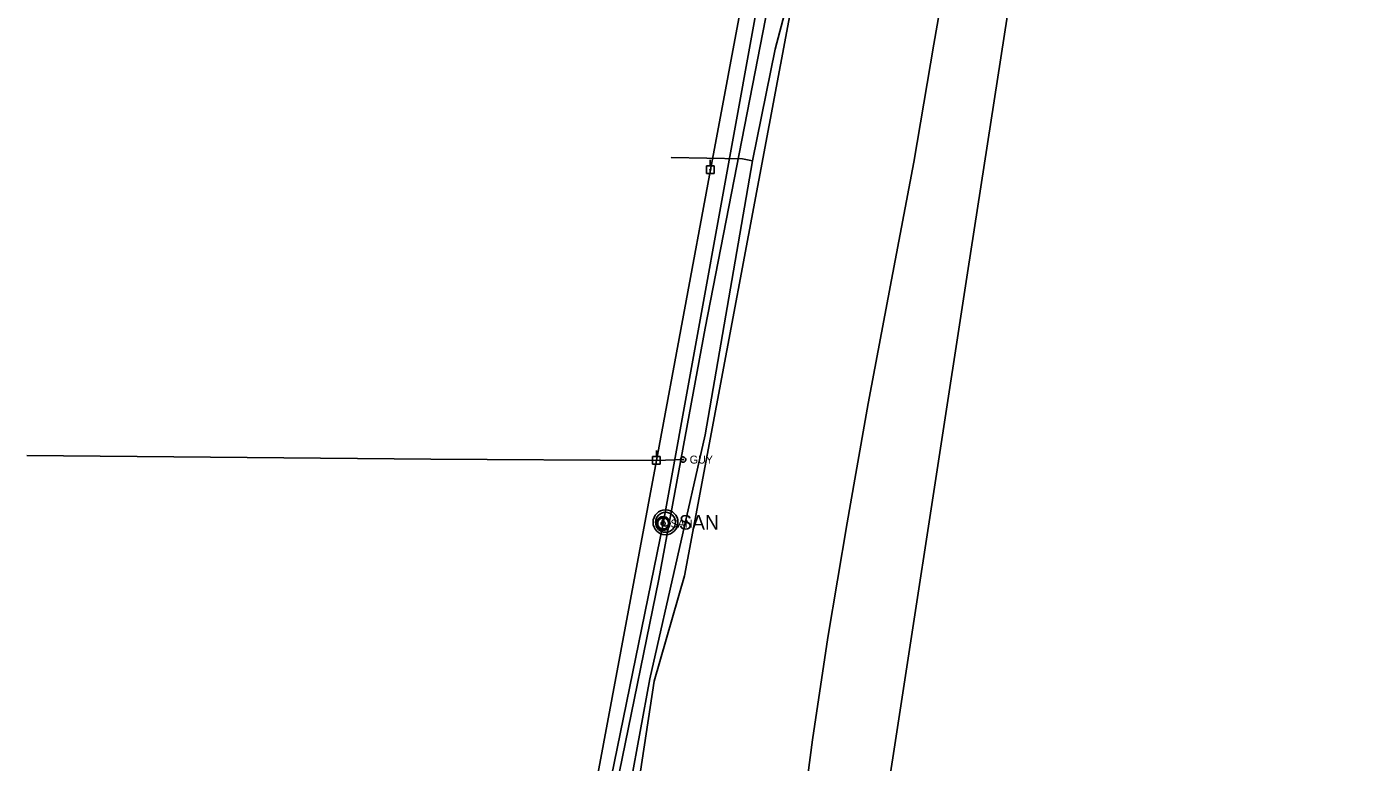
# Model space of a CAD drawing. Extents: x 600849 to 606371, y 330010 to 403088.
# Drawn here: x 601573 to 602215, y 355969 to 356323 of the extents above; entities that cross this region are included whole.
import ezdxf

# ---------------------------------------------------------------- set-up
doc = ezdxf.new("R2010")
doc.units = 0
for name, color, linetype in [('E_FTMS_Conduit', 7, 'Continuous'), ('E_UTL_EGuyWire', 7, 'Continuous'), ('E_UTL_EPowerPole', 7, 'Continuous'), ('E_UTL_FO_UG_QWEST', 7, 'Continuous'), ('E_UTL_G_UG', 7, 'Continuous'), ('E_UTL_Overhead', 7, 'Continuous'), ('E_UTL_SAN', 7, 'Continuous'), ('E_UTL_SAN_UG', 7, 'Continuous'), ('E_UTL_T_UG', 7, 'Continuous')]:
    doc.layers.add(name, color=color, linetype=linetype)

msp = doc.modelspace()

# ---------------------------------------------------------------- linework, layer by layer
at = {"layer": 'E_FTMS_Conduit'}
msp.add_lwpolyline([(601982.31, 355922.69), (602025.74, 356205), (602072.04, 356504.09), (602115.89, 356782.89), (602162.05, 357069.13), (602196.81, 357307.9), (602214.61, 357448.42)], dxfattribs=at)
at = {"layer": 'E_UTL_EGuyWire'}
msp.add_line((601888.89, 356115.12), (601876.1, 356114.7), dxfattribs=at)
for points in [[(601890.17, 356115.12), (601890.15, 356115.36), (601890.08, 356115.59), (601889.97, 356115.81), (601889.82, 356116), (601889.63, 356116.16), (601889.42, 356116.29), (601889.19, 356116.36), (601888.95, 356116.4), (601888.7, 356116.39), (601888.47, 356116.33), (601888.24, 356116.23), (601888.05, 356116.09), (601887.88, 356115.91), (601887.75, 356115.71), (601887.65, 356115.48), (601887.61, 356115.24), (601887.61, 356115), (601887.65, 356114.76), (601887.75, 356114.53), (601887.88, 356114.32), (601888.05, 356114.15), (601888.24, 356114.01), (601888.47, 356113.91), (601888.7, 356113.85), (601888.95, 356113.84), (601889.19, 356113.87), (601889.42, 356113.95), (601889.63, 356114.07), (601889.82, 356114.23), (601889.97, 356114.42), (601890.08, 356114.64), (601890.15, 356114.87), (601890.17, 356115.12)], [(601889.05, 356115.12), (601889.04, 356115.15), (601889.04, 356115.18), (601889.02, 356115.2), (601889, 356115.23), (601888.98, 356115.25), (601888.95, 356115.26), (601888.92, 356115.27), (601888.89, 356115.28), (601888.86, 356115.28), (601888.83, 356115.27), (601888.81, 356115.26), (601888.78, 356115.24), (601888.76, 356115.22), (601888.74, 356115.19), (601888.73, 356115.16), (601888.73, 356115.13), (601888.73, 356115.1), (601888.73, 356115.07), (601888.74, 356115.04), (601888.76, 356115.02), (601888.78, 356115), (601888.81, 356114.98), (601888.83, 356114.97), (601888.86, 356114.96), (601888.89, 356114.96), (601888.92, 356114.96), (601888.95, 356114.97), (601888.98, 356114.99), (601889, 356115.01), (601889.02, 356115.03), (601889.04, 356115.06), (601889.04, 356115.09), (601889.05, 356115.12)]]:
    msp.add_lwpolyline(points, dxfattribs=at)
at = {"layer": 'E_UTL_EPowerPole'}
for points in [[(601901.99, 356256.42), (601901.99, 356259.33)], [(601903.84, 356256.42), (601900.15, 356256.42)], [(601900.15, 356256.42), (601900.15, 356252.73)], [(601900.15, 356252.73), (601903.84, 356252.73)], [(601902.26, 356254.58), (601902.26, 356254.62), (601902.25, 356254.67), (601902.23, 356254.71), (601902.2, 356254.74), (601902.16, 356254.77), (601902.13, 356254.79), (601902.08, 356254.81), (601902.04, 356254.82), (601901.99, 356254.81), (601901.95, 356254.8), (601901.91, 356254.78), (601901.87, 356254.76), (601901.84, 356254.72), (601901.81, 356254.69), (601901.8, 356254.64), (601901.79, 356254.6), (601901.79, 356254.55), (601901.8, 356254.51), (601901.81, 356254.47), (601901.84, 356254.43), (601901.87, 356254.4), (601901.91, 356254.37), (601901.95, 356254.35), (601901.99, 356254.34), (601902.04, 356254.34), (601902.08, 356254.35), (601902.13, 356254.36), (601902.16, 356254.38), (601902.2, 356254.41), (601902.23, 356254.45), (601902.25, 356254.49), (601902.26, 356254.53), (601902.26, 356254.58)], [(601903.84, 356252.73), (601903.84, 356256.42)], [(601876.06, 356116.54), (601876.06, 356119.45)], [(601877.91, 356116.54), (601874.22, 356116.54)], [(601874.22, 356116.54), (601874.22, 356112.85)], [(601874.22, 356112.85), (601877.91, 356112.85)], [(601876.33, 356114.7), (601876.33, 356114.74), (601876.32, 356114.79), (601876.3, 356114.83), (601876.27, 356114.86), (601876.23, 356114.89), (601876.2, 356114.91), (601876.15, 356114.93), (601876.11, 356114.94), (601876.06, 356114.93), (601876.02, 356114.92), (601875.98, 356114.9), (601875.94, 356114.88), (601875.91, 356114.85), (601875.88, 356114.81), (601875.87, 356114.76), (601875.86, 356114.72), (601875.86, 356114.67), (601875.87, 356114.63), (601875.88, 356114.59), (601875.91, 356114.55), (601875.94, 356114.52), (601875.98, 356114.49), (601876.02, 356114.47), (601876.06, 356114.46), (601876.11, 356114.46), (601876.15, 356114.47), (601876.2, 356114.48), (601876.23, 356114.5), (601876.27, 356114.53), (601876.3, 356114.57), (601876.32, 356114.61), (601876.33, 356114.65), (601876.33, 356114.7)], [(601877.91, 356112.85), (601877.91, 356116.54)]]:
    msp.add_lwpolyline(points, dxfattribs=at)
at = {"layer": 'E_UTL_FO_UG_QWEST'}
msp.add_lwpolyline([(601944.01, 355926.93), (601951.12, 355980.3), (601958.59, 356029.58), (601967.76, 356084.77), (601971.53, 356105.69), (601977.93, 356142.12), (601989.06, 356201.56), (601999.81, 356258.26), (602009.42, 356314.96), (602018.86, 356368.21), (602029.07, 356415.09), (602035.02, 356458.54), (602045.75, 356506.54), (602051.67, 356553.69), (602055.69, 356605.2), (602058.29, 356661.71), (602061.14, 356712.21)], dxfattribs=at)
at = {"layer": 'E_UTL_G_UG'}
for points in [[(601889.56, 356059.22), (601940.72, 356331.55), (601950.67, 356396.26), (601952.22, 356402.97), (601955.47, 356427.77), (601958.53, 356439.7), (601968.64, 356468.31), (601975.69, 356493.38), (601983.67, 356527.58), (601985.35, 356570.92), (601985.53, 356608.34), (601987.94, 356664.73), (601988.66, 356716.6), (601989.42, 356760.92), (601990.64, 356790.59), (601990.85, 356856.87), (601990.66, 356932.13), (601990.35, 356983.12), (601990.5, 356985.48), (601990.78, 357017.61)], [(601872.98, 356009.68), (601899.57, 356127.09), (601922.23, 356258.91), (601933.22, 356312.53), (601938.27, 356332.06), (601948.22, 356396.73), (601949.76, 356403.42), (601953.01, 356428.25), (601956.14, 356440.43), (601966.26, 356469.06), (601973.27, 356494), (601981.18, 356527.91), (601982.85, 356570.97), (601983.03, 356608.4), (601985.44, 356664.8), (601986.17, 356716.64)], [(601883.21, 356260.45), (601883.2, 356260.51), (601917.54, 356259.83), (601922.23, 356258.91)], [(601889.56, 356059.22), (601875.05, 356008.59)], [(601875.05, 356008.59), (601867.23, 355957.76), (601857.32, 355902.22), (601843.21, 355832.17), (601833.35, 355780.42), (601829.89, 355766.73)], [(601872.98, 356009.68), (601863.58, 355958.96), (601853.83, 355902.97), (601836.75, 355823.58), (601830.42, 355780.41)]]:
    msp.add_lwpolyline(points, dxfattribs=at)
at = {"layer": 'E_UTL_Overhead'}
for points in [[(601775.11, 355493.17), (601794.88, 355632.14), (601813.19, 355774.43), (601846.41, 355956.03), (601876.1, 356114.7), (601902.03, 356254.58), (601928.02, 356393.42), (601947.92, 356557.45), (601949.4, 356721.2), (601951.31, 356874.93), (601952.99, 357026.21), (601955.32, 357157.12), (601956.05, 357297.31), (601956.02, 357419.23)], [(601573.22, 356117.17), (601767.66, 356115.35), (601876.1, 356114.7)]]:
    msp.add_lwpolyline(points, dxfattribs=at)
at = {"layer": 'E_UTL_SAN'}
for points in [[(601882.62, 356084.39), (601882.56, 356085.01), (601882.38, 356085.62), (601882.09, 356086.17), (601881.71, 356086.67), (601881.23, 356087.08), (601880.69, 356087.39), (601880.1, 356087.6), (601879.47, 356087.69), (601878.85, 356087.66), (601878.24, 356087.51), (601877.67, 356087.25), (601877.16, 356086.88), (601876.72, 356086.43), (601876.38, 356085.9), (601876.15, 356085.32), (601876.03, 356084.7), (601876.03, 356084.08), (601876.15, 356083.46), (601876.38, 356082.88), (601876.72, 356082.35), (601877.16, 356081.9), (601877.67, 356081.53), (601878.24, 356081.27), (601878.85, 356081.12), (601879.47, 356081.09), (601880.1, 356081.18), (601880.69, 356081.39), (601881.23, 356081.7), (601881.71, 356082.11), (601882.09, 356082.6), (601882.38, 356083.16), (601882.56, 356083.76), (601882.62, 356084.39)], [(601881.96, 356084.39), (601881.91, 356084.89), (601881.77, 356085.37), (601881.54, 356085.82), (601881.23, 356086.21), (601880.85, 356086.54), (601880.41, 356086.79), (601879.94, 356086.95), (601879.44, 356087.03), (601878.94, 356087), (601878.45, 356086.88), (601878, 356086.68), (601877.59, 356086.38), (601877.24, 356086.02), (601876.97, 356085.6), (601876.78, 356085.13), (601876.69, 356084.64), (601876.69, 356084.14), (601876.78, 356083.65), (601876.97, 356083.18), (601877.24, 356082.76), (601877.59, 356082.39), (601878, 356082.1), (601878.45, 356081.89), (601878.94, 356081.78), (601879.44, 356081.75), (601879.94, 356081.82), (601880.41, 356081.99), (601880.85, 356082.24), (601881.23, 356082.57), (601881.54, 356082.96), (601881.77, 356083.41), (601881.91, 356083.89), (601881.96, 356084.39)], [(601880.31, 356084.39), (601880.29, 356084.58), (601880.24, 356084.76), (601880.15, 356084.92), (601880.03, 356085.07), (601879.89, 356085.2), (601879.73, 356085.29), (601879.55, 356085.35), (601879.37, 356085.38), (601879.18, 356085.37), (601878.99, 356085.32), (601878.82, 356085.25), (601878.67, 356085.14), (601878.54, 356085), (601878.44, 356084.84), (601878.37, 356084.67), (601878.33, 356084.48), (601878.33, 356084.29), (601878.37, 356084.11), (601878.44, 356083.94), (601878.54, 356083.78), (601878.67, 356083.64), (601878.82, 356083.53), (601878.99, 356083.45), (601879.18, 356083.41), (601879.37, 356083.4), (601879.55, 356083.43), (601879.73, 356083.49), (601879.89, 356083.58), (601880.03, 356083.71), (601880.15, 356083.85), (601880.24, 356084.02), (601880.29, 356084.2), (601880.31, 356084.39)]]:
    msp.add_lwpolyline(points, dxfattribs=at)
for radius in [6, 4.8, 1.8]:
    msp.add_circle((601880.45, 356084.96), radius, dxfattribs=at)
at = {"layer": 'E_UTL_SAN_UG'}
for p, q in [((601879.32, 356084.39), (601926.46, 356343.91)), ((601825.37, 355821.01), (601879.32, 356084.39))]:
    msp.add_line(p, q, dxfattribs=at)
at = {"layer": 'E_UTL_T_UG'}
msp.add_lwpolyline([(601858.24, 355964.25), (601877.3, 356057.56), (601899.52, 356178.33), (601929.77, 356333.82), (601938.25, 356367.13), (601952.25, 356440.33), (601965.82, 356525.1), (601974.27, 356640.33), (601978.84, 356798.65), (601979.4, 356921.27), (601981.27, 357066.58), (601982.24, 357217.34), (601985.65, 357358.94), (601986.41, 357428.06)], dxfattribs=at)

# ---------------------------------------------------------------- texts
at = {"layer": 'E_UTL_EGuyWire'}
msp.add_text('GUY', height=3.85, dxfattribs=at).set_placement((601892.09, 356113.19))
at = {"layer": 'E_UTL_SAN'}
for height, p in [(3.849, (601882.88, 356082.44)), (6.998, (601886.93, 356081.42))]:
    msp.add_text('SAN', height=height, dxfattribs=at).set_placement(p)

doc.saveas('drawing.dxf')
